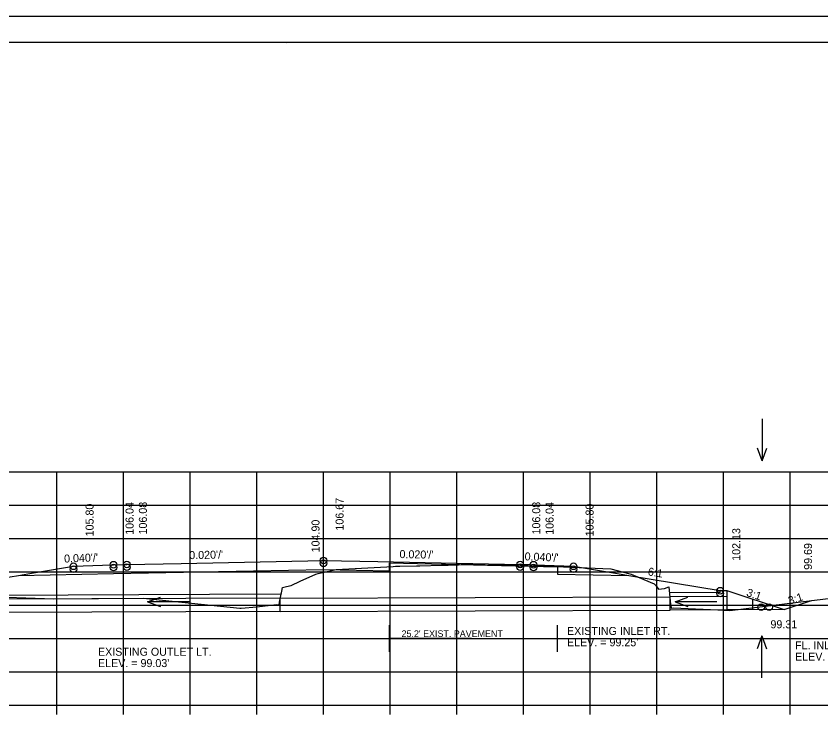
# Model space of a CAD drawing. Extents: x 1175611 to 1176402, y -433344 to -416213.
# Drawn here: x 1175734.9 to 1175855.6, y -432595.6 to -432490.2 of the extents above; entities that cross this region are included whole.
import ezdxf

# ---------------------------------------------------------------- set-up
doc = ezdxf.new("R2010")
doc.units = 0
for name, color, linetype in [('R_Alt Surface', 7, 'Continuous'), ('R_Axis', 7, 'Continuous'), ('R_Border', 7, 'Continuous'), ('R_Draft', 7, 'Continuous'), ('R_Drive', 7, 'Continuous'), ('R_Exist Surface', 7, 'Continuous'), ('R_Fin Surface', 7, 'Continuous'), ('R_Grid', 7, 'Continuous'), ('R_No Plot', 7, 'Continuous'), ('R_Water', 7, 'Continuous'), ('R_Water Annot', 7, 'Continuous'), ('R_Xsect Elev', 7, 'Continuous'), ('R_Xsect Slope', 7, 'Continuous')]:
    doc.layers.add(name, color=color, linetype=linetype)

msp = doc.modelspace()

# ---------------------------------------------------------------- linework, layer by layer
at = {"layer": 'R_Alt Surface'}
msp.add_lwpolyline([(1175735.2, -432574.11), (1175749.48, -432573.82), (1175780.98, -432573.19), (1175790.85, -432573.39), (1175790.85, -432572.22), (1175816.06, -432572.8), (1175816.06, -432573.89), (1175826.75, -432574.11)], dxfattribs=at)
at = {"layer": 'R_Axis'}
for p, q in [((1175640.97, -432593.54), (1175920.97, -432593.54)), ((1175740.97, -432594.94), (1175740.97, -432593.54)), ((1175750.97, -432594.94), (1175750.97, -432593.54)), ((1175760.97, -432594.94), (1175760.97, -432593.54)), ((1175770.97, -432594.94), (1175770.97, -432593.54)), ((1175780.97, -432594.94), (1175780.97, -432593.54)), ((1175790.97, -432594.94), (1175790.97, -432593.54)), ((1175800.97, -432594.94), (1175800.97, -432593.54)), ((1175810.97, -432594.94), (1175810.97, -432593.54)), ((1175820.97, -432594.94), (1175820.97, -432593.54)), ((1175830.97, -432594.94), (1175830.97, -432593.54)), ((1175840.97, -432594.94), (1175840.97, -432593.54)), ((1175850.97, -432594.94), (1175850.97, -432593.54))]:
    msp.add_line(p, q, dxfattribs=at)
at = {"layer": 'R_Border'}
for p, q in [((1175622.97, -432494.08), (1175939.15, -432494.08)), ((1175775.49, -432494.34), (1175775.49, -432494.34)), ((1175775.49, -432494.34), (1175775.49, -432494.34))]:
    msp.add_line(p, q, dxfattribs=at)
at = {"layer": 'R_Draft'}
for q in [(1175790.85, -432583.56), (1175816.06, -432583.56)]:
    msp.add_line((1175803.17, -432583.56), q, dxfattribs=at)
for points in [[(1175790.85, -432585.56), (1175790.85, -432581.56)], [(1175816.06, -432585.56), (1175816.06, -432581.56)]]:
    msp.add_lwpolyline(points, dxfattribs=at)
at = {"layer": 'R_Drive'}
for p, q in [((1175840.47, -432576.35), (1175841.47, -432576.35)), ((1175841.47, -432576.35), (1175841.47, -432579.25)), ((1175845.3, -432577.63), (1175845.3, -432579.25))]:
    msp.add_line(p, q, dxfattribs=at)
at = {"layer": 'R_Exist Surface'}
msp.add_lwpolyline([(1175729.32, -432577.21), (1175740.5, -432577.62), (1175753.93, -432577.53), (1175768.4, -432579.02), (1175768.59, -432579), (1175768.64, -432579), (1175770.99, -432578.8), (1175773.92, -432578.47), (1175774.34, -432578.53), (1175774.38, -432578.09), (1175774.7, -432576.45), (1175774.8, -432575.89), (1175775.43, -432575.75), (1175776.1, -432575.6), (1175777.47, -432574.95), (1175779.81, -432573.91), (1175780.18, -432573.82), (1175782.85, -432573.2), (1175790.49, -432572.79), (1175791.43, -432572.74), (1175791.77, -432572.72), (1175791.95, -432572.71), (1175792.44, -432572.7), (1175794.92, -432572.65), (1175795.42, -432572.64), (1175798.67, -432572.57), (1175799.67, -432572.55), (1175801.21, -432572.5), (1175801.62, -432572.48), (1175803.1, -432572.45), (1175803.17, -432572.45), (1175803.24, -432572.45), (1175803.67, -432572.46), (1175805.06, -432572.51), (1175805.24, -432572.52), (1175806.01, -432572.55), (1175807.71, -432572.56), (1175808.31, -432572.57), (1175809.23, -432572.58), (1175809.96, -432572.6), (1175811.66, -432572.67), (1175813.2, -432572.7), (1175813.71, -432572.72), (1175814.52, -432572.69), (1175814.72, -432572.68), (1175815.79, -432572.74), (1175824.06, -432573.11), (1175826.92, -432573.88), (1175827.1, -432573.9), (1175829.03, -432574.72), (1175830.55, -432575.34), (1175830.8, -432575.63), (1175831.21, -432576.17), (1175832.13, -432576.05), (1175832.77, -432575.81), (1175833.04, -432578.48), (1175833.06, -432578.51), (1175833.13, -432579.02), (1175833.48, -432578.97), (1175840.14, -432579.24), (1175841.94, -432579.34), (1175876.76, -432575.13)], dxfattribs=at)
at = {"layer": 'R_Fin Surface'}
msp.add_lwpolyline([(1175731.43, -432574.73), (1175735.2, -432574.11), (1175737.48, -432573.73), (1175743.48, -432572.73), (1175747.83, -432572.55), (1175749.48, -432572.49), (1175750.93, -432572.46), (1175751.48, -432572.45), (1175759.6, -432572.29), (1175780.98, -432571.86), (1175789.1, -432572.02), (1175810.48, -432572.45), (1175811.93, -432572.48), (1175812.48, -432572.49), (1175814.13, -432572.55), (1175818.48, -432572.73), (1175824.48, -432573.73), (1175826.75, -432574.11), (1175840.47, -432576.35), (1175841.47, -432576.35), (1175850.08, -432579.22), (1175854.15, -432577.87)], dxfattribs=at)
msp.add_lwpolyline([(1175731.43, -432574.73), (1175735.2, -432574.11), (1175737.48, -432573.73), (1175743.48, -432572.73), (1175747.83, -432572.55), (1175749.48, -432572.49), (1175750.93, -432572.46), (1175751.48, -432572.45), (1175759.6, -432572.29), (1175780.98, -432571.86), (1175789.1, -432572.02), (1175810.48, -432572.45), (1175811.93, -432572.48), (1175812.48, -432572.49), (1175814.13, -432572.55), (1175818.48, -432572.73), (1175824.48, -432573.73), (1175826.75, -432574.11), (1175840.47, -432576.35), (1175841.47, -432576.35), (1175850.08, -432579.22), (1175854.15, -432577.87)], dxfattribs=at)
at = {"layer": 'R_Grid'}
for p, q in [((1175640.97, -432558.54), (1175920.97, -432558.54)), ((1175740.97, -432593.54), (1175740.97, -432558.54)), ((1175750.97, -432593.54), (1175750.97, -432558.54)), ((1175760.97, -432593.54), (1175760.97, -432558.54)), ((1175770.97, -432593.54), (1175770.97, -432558.54)), ((1175780.97, -432593.54), (1175780.97, -432558.54)), ((1175790.97, -432593.54), (1175790.97, -432558.54)), ((1175800.97, -432593.54), (1175800.97, -432558.54)), ((1175810.97, -432593.54), (1175810.97, -432558.54)), ((1175820.97, -432593.54), (1175820.97, -432558.54)), ((1175830.97, -432593.54), (1175830.97, -432558.54)), ((1175840.97, -432593.54), (1175840.97, -432558.54)), ((1175850.97, -432593.54), (1175850.97, -432558.54)), ((1175640.97, -432563.54), (1175920.97, -432563.54)), ((1175640.97, -432568.54), (1175920.97, -432568.54)), ((1175640.97, -432573.54), (1175920.97, -432573.54)), ((1175640.97, -432578.54), (1175920.97, -432578.54)), ((1175640.97, -432583.54), (1175920.97, -432583.54)), ((1175640.97, -432588.54), (1175920.97, -432588.54)), ((1175640.97, -432593.54), (1175920.97, -432593.54))]:
    msp.add_line(p, q, dxfattribs=at)
at = {"layer": 'R_No Plot'}
msp.add_line((1175610.57, -432490.18), (1175943.91, -432490.18), dxfattribs=at)
msp.add_lwpolyline([(1175610.57, -432490.18), (1175943.91, -432490.18), (1175943.91, -432703.52), (1175610.57, -432703.52)], close=True, dxfattribs=at)
for centre in [(1175743.48, -432572.73), (1175749.48, -432572.49), (1175751.48, -432572.45), (1175780.98, -432571.86), (1175780.98, -432572.28), (1175810.48, -432572.45), (1175812.48, -432572.49), (1175818.48, -432572.73), (1175743.48, -432573.15), (1175749.48, -432572.91), (1175751.48, -432572.87), (1175810.48, -432572.87), (1175812.48, -432572.91), (1175818.48, -432573.15), (1175840.48, -432576.39), (1175840.48, -432576.82), (1175846.62, -432578.87), (1175847.83, -432578.85), (1175847.83, -432578.85)]:
    msp.add_circle(centre, 0.5, dxfattribs=at)
at = {"layer": 'R_Water'}
for p, q in [((1175774.48, -432576.93), (1175720.25, -432577.13)), ((1175840.47, -432576.68), (1175832.97, -432576.71)), ((1175840.47, -432576.68), (1175840.47, -432576.35)), ((1175774.48, -432577.51), (1175719.25, -432577.71)), ((1175774.48, -432577.51), (1175832.96, -432577.29)), ((1175774.49, -432579.51), (1175774.48, -432577.51)), ((1175832.97, -432579.29), (1175832.96, -432577.29)), ((1175841.47, -432577.25), (1175832.97, -432577.29)), ((1175774.49, -432579.51), (1175710.41, -432579.75)), ((1175774.49, -432579.51), (1175832.97, -432579.29)), ((1175850.08, -432579.22), (1175832.97, -432579.29))]:
    msp.add_line(p, q, dxfattribs=at)
at = {"layer": 'R_Water Annot'}
for p, q in [((1175846.79, -432550.63), (1175846.79, -432556.92)), ((1175846.79, -432556.92), (1175846.09, -432554.99)), ((1175846.79, -432556.92), (1175847.49, -432554.99)), ((1175754.59, -432578.07), (1175756.52, -432577.37)), ((1175760.88, -432578.07), (1175754.59, -432578.07)), ((1175754.59, -432578.07), (1175756.52, -432578.77)), ((1175833.7, -432578.07), (1175835.63, -432577.37)), ((1175839.99, -432578.07), (1175833.7, -432578.07)), ((1175833.7, -432578.07), (1175835.63, -432578.77)), ((1175846.71, -432583.18), (1175846.01, -432585.1)), ((1175846.71, -432589.46), (1175846.71, -432583.18)), ((1175846.71, -432583.18), (1175847.41, -432585.1))]:
    msp.add_line(p, q, dxfattribs=at)

# ---------------------------------------------------------------- texts
at = {"layer": 'R_Draft'}
msp.add_text("25.2' EXIST. PAVEMENT", height=1, dxfattribs=at).set_placement((1175792.68, -432583.34))
at = {"layer": 'R_Water Annot'}
for s, p in [('EXISTING INLET RT.', (1175817.49, -432583.03)), ("ELEV. = 99.25'", (1175817.49, -432584.73)), ('FL. INLET RT.', (1175851.7, -432585.18)), ('EXISTING OUTLET LT.', (1175747.14, -432586.15)), ("ELEV. = 99.03'", (1175747.14, -432587.85)), ("ELEV. = 99.31'", (1175851.7, -432586.88))]:
    msp.add_text(s, height=1.2, dxfattribs=at).set_placement(p)
at = {"layer": 'R_Xsect Elev'}
for s, p in [('106.67', (1175783.98, -432567.37)), ('105.80', (1175746.48, -432568.24)), ('106.04', (1175752.48, -432568)), ('106.08', (1175754.48, -432567.96)), ('106.08', (1175813.48, -432567.96)), ('106.04', (1175815.48, -432568)), ('105.80', (1175821.48, -432568.24)), ('104.90', (1175780.37, -432570.64)), ('102.13', (1175843.48, -432571.91)), ('99.69', (1175854.25, -432573.26))]:
    msp.add_text(s, height=1.2, rotation=90, dxfattribs=at).set_placement(p)
msp.add_text('99.31', height=1.2, dxfattribs=at).set_placement((1175848.01, -432582.03))
at = {"layer": 'R_Xsect Slope'}
for s, rotation, p in [("0.040'/'", 2.2906, (1175742.08, -432572.18)), ("0.020'/'", 1.1458, (1175760.84, -432571.66)), ("0.020'/'", 358.8542, (1175792.36, -432571.49)), ("0.040'/'", 357.7094, (1175811.12, -432571.83)), ('6:1', 350.5377, (1175829.56, -432574.07)), ('3:1', 341.5651, (1175844.31, -432577.15)), ('3:1', 18.4349, (1175850.89, -432578.5))]:
    msp.add_text(s, height=1.2, rotation=rotation, dxfattribs=at).set_placement(p)

doc.saveas('drawing.dxf')
